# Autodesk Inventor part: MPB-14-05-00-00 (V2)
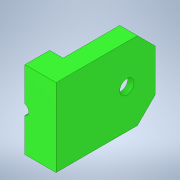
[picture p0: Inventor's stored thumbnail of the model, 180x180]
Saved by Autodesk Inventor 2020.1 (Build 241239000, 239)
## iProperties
Created: 2020-04
Part Number: MPB-14-05-00-00 (V2)
Material: Al 7075
Document SubType Name: Modeling
Designer: Safarabadi
Density: 8.47 g/cm^3
Appearance: Aluminum - Flat
Author: Safarabadi
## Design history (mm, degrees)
derived "MPB-14-05-00-00.ipt"
feature "Solid1::MPB-14-05-00-00.ipt" dims "d0" = 10
tag "TaggingFeature1"
body "Solid1"
